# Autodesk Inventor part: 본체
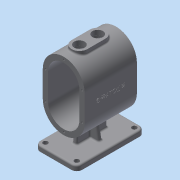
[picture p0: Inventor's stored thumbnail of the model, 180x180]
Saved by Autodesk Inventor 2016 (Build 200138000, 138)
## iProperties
Created: 2016-12
Part Number: 본체
Material: 알루미늄 6061
Document SubType Name: Modeling
Designer: mduedu
Density: 2.71 g/cm^3
Mass: 1171.02 g
Surface Area: 1014.94 cm^2
Volume: 432.112 cm^3
Appearance: 기본값
Author: mduedu
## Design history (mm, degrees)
sketch "스케치1"
  geometry: L1 (40, -25)-(40, 25); L2 (-40, 25)-(-40, -25); L3 (-40, -25)-(40, 25); L4 (40, -25)-(-40, 25); L5 (0, 25)-(0, -25); A1 r 40 centre (0, 25) between (40, 25) and (-40, 25); A2 r 40 centre (0, -25) between (-40, -25) and (40, -25); 1 further point
  constraints: 10 end point, 4 point on circle, 3 tangent, 2 centre point, 2 midpoint, 2 parallel, 1 vertical
  dimensions: "d0" = 130 dimension on A2 A1; "d2" = 80 distance between parallel lines of L1 L2
extrude "돌출1" new body sketch "스케치1" stored distance "d3" = 100; taper "d4" = 0 deg
feature "쉘1" dims "d5" = 10
sketch "스케치2"
  geometry: L1 (-90, 65)-(-100, 65); L2 (-100, 65)-(-100, -65); L3 (-100, -65)-(-90, -65); L4 (-90, -65)-(-90, 65); 2 further points
  constraints: 8 end point, 2 parallel, 1 horizontal, 1 horizontal alignment, 1 midpoint, 1 perpendicular
  dimensions: "d6" = 100 distance from line of L2 point (0, 0); "d7" = 130 distance of L1.end L2.end; "d8" = 10 distance of L2.end L3.end
extrude "돌출2" join sketch "스케치2" stored distance "d9" = 80; taper "d10" = 0 deg
fillet "모깎기1" dims "d11" = 10
sketch "스케치3"
  geometry: L1 (-10, 10)-(-10, 120) reference; L2 (60, 0)-(0, 0) reference; L3 (70, 120)-(70, 10) reference; L4 (0, 130)-(60, 130) reference; A1 r 10 centre (0, 120) between (0, 130) and (-10, 120) reference; A2 r 10 centre (0, 10) between (-10, 10) and (0, 0) reference; A3 r 10 centre (60, 10) between (60, 0) and (70, 10) reference; A4 r 10 centre (60, 120) between (70, 120) and (60, 130) reference; 5 further points
  constraints: 4 coincident
hole "구멍1" sketch "스케치3" at (60, 120), (60, 10), (0, 10), (0, 120) diameter "d12" = 9; stored, may be unused: countersink angle "d16" = 90 deg, drill point angle "d18" = 118 deg; dims "d13" = 6, "d14" = 4, "d15" = 2, "d17" = 8
sketch "스케치5"
  geometry: L1 (34, 35)-(26, 35); L2 (26, 35)-(26, 95); L3 (26, 95)-(34, 95); L4 (34, 95)-(34, 35); L5 (34, 35)-(26, 95); L6 (26, 35)-(34, 95); 1 further point
  constraints: 12 end point, 2 midpoint, 2 parallel, 1 horizontal, 1 perpendicular
  dimensions: "d22" = 8 distance of L2.end L3.end; "d24" = 60 distance of L1.end L2.end
extrude "돌출3" join sketch "스케치5" stored distance "d25" = 80; taper "d26" = 0 deg
feature "면 기울기1" dims angle "d27" = 5 deg
sketch "스케치6"
  geometry: L1 (-30, -90)-(30, -90) reference; L2 (-15.072, -62.052)-(-20, -90); A1 r 40 centre (0, -25) between (-40, -25) and (40, -25) reference; 1 further point
  constraints: 2 end point, 1 point on circle, 1 point on line
  dimensions: "d28" = 20 horizontal distance of A1.centre L2.end; "d29" = 80 deg angle of L2 L1
feature "리브1" sketch "스케치6" dims "d30" = 1, "d31" = 8, "d32" = 0, "d33" = 0, "d34" = 1, "d35" = 1
fillet "모깎기2" dims "d36" = 3
fillet "모깎기3" dims "d37" = 3, "d38" = 3
node "작업 평면1"
sketch "스케치9"
  geometry: 1 further point
sketch "스케치7"
  geometry: L1 (40, 50)-(-40, 50) reference; C1 r 15 at (0, 20); 1 further point
  constraints: 1 centre point, 1 vertical alignment
  dimensions: "d40" = 30 diameter of C1; "d41" = 30 distance from line of C1.centre L1
extrude "돌출4" join sketch "스케치7" stored distance "d42" = 80; taper "d43" = 0 deg
sketch "스케치15"
  geometry: C1 r 15 at (0, -15); C2 r 15 at (0, 20) reference; 1 further point
  constraints: 1 centre point, 1 vertical alignment
  dimensions: "d83" = 30 diameter of C1; "d84" = 35 distance of C1.centre C2.centre
extrude "돌출6" join sketch "스케치15" stored distance "d85" = 10; taper "d86" = 0 deg
hole "구멍2" diameter "d46" = 20; stored, may be unused: countersink angle "d50" = 90 deg, drill point angle "d52" = 118 deg; dims "d44" = 10, "d45" = 10, "d47" = 6, "d48" = 4, "d49" = 2, "d51" = 8
hole "구멍6" diameter "d89" = 20; stored, may be unused: countersink angle "d93" = 90 deg, drill point angle "d95" = 118 deg; dims "d87" = 10, "d88" = 10, "d90" = 6, "d91" = 4, "d92" = 2, "d94" = 8
node "작업 평면2"
sketch "스케치8"
  geometry: C1 r 15 at (0, 0) reference; C2 r 15 at (0, 0); 1 further point
  constraints: 1 centre point, 1 coincident
  dimensions: "d55" = 30 diameter of C2
extrude "돌출5" cut sketch "스케치8" stored distance "d56" = 80; taper "d57" = 0 deg
sketch "스케치16"
  geometry: C1 r 15 at (0, 35); 2 further points
  constraints: 1 centre point, 1 coincident, 1 vertical alignment
  dimensions: "d96" = 30 diameter of C1
extrude "돌출7" cut sketch "스케치16" stored distance "d97" = 10; taper "d98" = 0 deg
sketch "스케치17"
  geometry: L1 (15, 0)-(15, -35); L2 (-15, 0)-(-15, -35); C1 r 10 at (0, 0) reference; C2 r 10 at (0, -35) reference; A1 r 15 centre (0, 0) between (15, 0) and (-15, 0) reference; A2 r 15 centre (0, -35) between (15, -35) and (-15, -35) reference; 1 further point
  constraints: 4 end point, 4 point on circle, 3 tangent, 1 vertical
extrude "돌출8" join sketch "스케치17" stored distance "d99" = 10; taper "d100" = 0 deg
fillet "모깎기5" dims "d101" = 3
chamfer "모따기1" distance "d58" = 1; stored, may be unused: second distance "d59" = 2, angle "d60" = 45 deg
sketch "스케치10"
  geometry: 2 further points
  constraints: 1 coincident, 1 other
feature "엠보싱1" sketch "스케치10" dims "d0" = 130, "d2" = 80, "d11" = 10, "d61" = 0.5, "d62" = 0
sketch "스케치11"
  geometry: 1 further point
hole "구멍3" sketch "스케치11" at (0, 60) diameter "d63" = 3.242; stored, may be unused: countersink angle "d67" = 90 deg, drill point angle "d69" = 120 deg; dims "d64" = 8.6, "d65" = 4, "d66" = 2, "d68" = 10.6
sketch "스케치12"
  geometry: 1 further point
hole "구멍5" sketch "스케치12" at (0, 60) diameter "d70" = 3.242; stored, may be unused: countersink angle "d74" = 90 deg, drill point angle "d76" = 120 deg; dims "d71" = 8.6, "d72" = 4, "d73" = 2, "d75" = 10.6
node "솔리드1"
mirror "대칭1"
pattern_linear "직사각형 패턴1"
pattern_linear "직사각형 패턴2"
node "투영된 루프1"
sketch "스케치13"
  geometry: L1 (-40, 25)-(-40, -25) reference; L2 (40, -25)-(40, 25) reference; L3 (35, 25)-(35, -25); L4 (-35, -25)-(-35, 25); A1 r 40 centre (0, 25) between (40, 25) and (-40, 25) reference; A2 r 40 centre (0, -25) between (-40, -25) and (40, -25) reference; A3 r 35 centre (0, 25) between (35, 25) and (-35, 25); A4 r 35 centre (0, -25) between (-35, -25) and (35, -25); 2 further points
  constraints: 5 point on circle, 4 end point, 2 centre point, 3 other
  dimensions: "d77" = 5 distance between parallel lines of L3 L2
sketch "스케치14"
  geometry: L1 (-40, 25)-(-40, -25) reference; L2 (40, -25)-(40, 25) reference; L3 (35, 25)-(35, -25); L4 (-35, -25)-(-35, 25); A1 r 40 centre (0, 25) between (40, 25) and (-40, 25) reference; A2 r 40 centre (0, -25) between (-40, -25) and (40, -25) reference; A3 r 35 centre (0, 25) between (35, 25) and (-35, 25); A4 r 35 centre (0, -25) between (-35, -25) and (35, -25); 2 further points
  constraints: 5 point on circle, 4 end point, 2 centre point, 3 other
  dimensions: "d80" = 5 distance between parallel lines of L2 L3
node "투영된 루프3"
node "투영된 루프4"
node "투영된 루프5"
